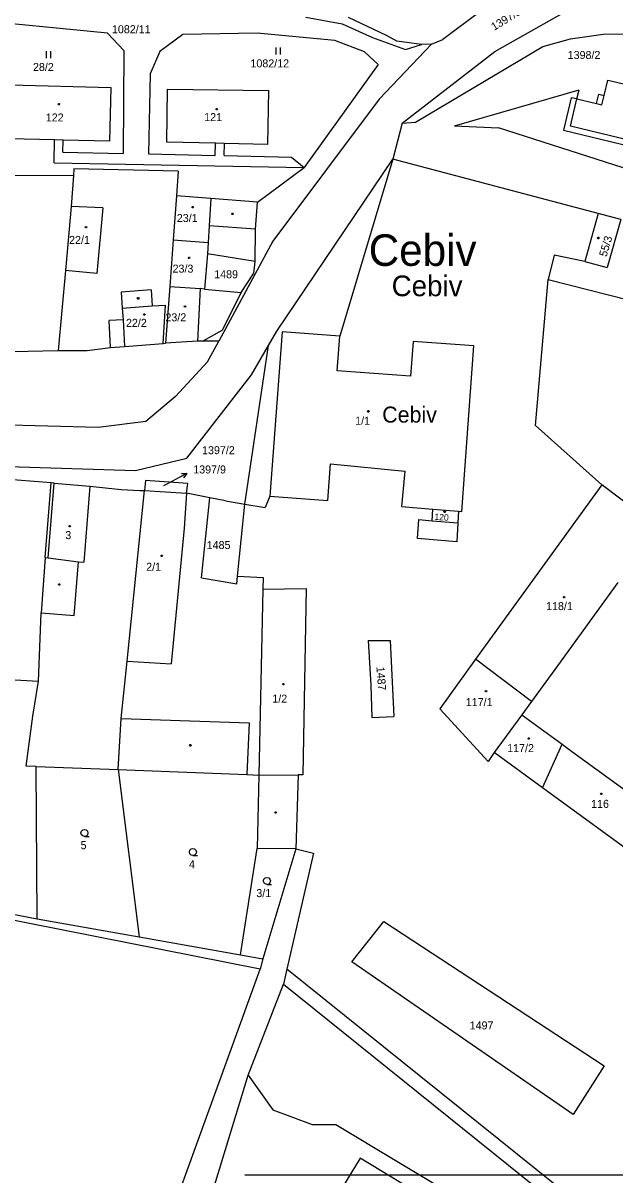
# Model space of a CAD drawing. Extents: x -852001 to -842497, y -1063614 to -1052182.
# Drawn here: x -849422.1 to -849296.3, y -1056500 to -1056255.4 of the extents above; entities that cross this region are included whole.
import ezdxf

# ---------------------------------------------------------------- set-up
doc = ezdxf.new("R2010")
doc.units = 0
for name, color, linetype in [('Default', 7, 'Continuous'), ('KLADY_ZMVM', 7, 'Continuous'), ('KN_HRANICE', 7, 'Continuous'), ('KN_KULTURY', 7, 'Continuous'), ('KN_PARCELY', 7, 'Continuous'), ('KN_SLUCKY', 7, 'Continuous')]:
    doc.layers.add(name, color=color, linetype=linetype)

# ---------------------------------------------------------------- blocks, each defined once
blk = doc.blocks.new('304')
at = {"layer": 'Default'}
blk.add_lwpolyline([(0, 0), (-0.38, 0.1), (-0.65, 0.37), (-0.75, 0.74), (-0.65, 1.11), (-0.38, 1.38), (-0.01, 1.48), (0.36, 1.38), (0.63, 1.11), (0.73, 0.73), (0.63, 0.35), (0.36, 0.08), (-0.02, -0.02), (0.98, -0.02)], dxfattribs=at)
blk = doc.blocks.new('306')
at = {"layer": 'Default'}
for p, q in [((-0.5, 1.5), (-0.5, 0)), ((0.5, 0), (0.5, 1.5))]:
    blk.add_line(p, q, dxfattribs=at)
blk = doc.blocks.new('NAHRADNI_SYMBOL')
at = {"layer": 'Default'}
blk.add_lwpolyline([(0.09, 0.15), (0.18, 0), (0.09, -0.15), (-0.09, -0.15), (-0.18, 0), (-0.09, 0.15), (0.09, 0.15)], dxfattribs=at)
blk = doc.blocks.new('10292')
at = {"layer": 'Default'}
blk.add_line((0, 3), (0, 0), dxfattribs=at)
blk.add_lwpolyline([(-0.5, 2), (0, 3), (0.5, 2)], dxfattribs=at)
blk = doc.blocks.new('402')
at = {"layer": 'Default'}
blk.add_lwpolyline([(0.09, 0.15), (0.18, 0), (0.09, -0.15), (-0.09, -0.15), (-0.18, 0), (-0.09, 0.15), (0.09, 0.15)], dxfattribs=at)

msp = doc.modelspace()

# ---------------------------------------------------------------- linework, layer by layer
at = {"layer": 'KLADY_ZMVM'}
msp.add_lwpolyline([(-849375, -1056500), (-848750, -1056500), (-848750, -1056000)], dxfattribs=at)
at = {"layer": 'KN_HRANICE'}
for p, q in [((-849321.82, -1056261.46), (-849300.76, -1056249.55)), ((-849324.78, -1056252.85), (-849332.91, -1056258.92)), ((-849362.03, -1056254.15), (-849354.27, -1056255.62)), ((-849344.89, -1056258.04), (-849352.94, -1056254.24)), ((-849404.18, -1056257.55), (-849424.4, -1056255.6)), ((-849400.7, -1056261.28), (-849404.18, -1056257.55)), ((-849388.12, -1056257.84), (-849393.05, -1056261.45)), ((-849372.35, -1056257.55), (-849388.12, -1056257.84)), ((-849355.83, -1056259.12), (-849372.35, -1056257.55)), ((-849354.27, -1056255.62), (-849347.82, -1056258.48)), ((-849305.78, -1056258.79), (-849298.81, -1056257.8)), ((-849298.81, -1056257.8), (-849292.01, -1056257.69)), ((-849349.55, -1056261.51), (-849355.83, -1056259.12)), ((-849347.82, -1056258.48), (-849340.83, -1056261.01)), ((-849335.32, -1056259.89), (-849346.41, -1056271.62)), ((-849342.67, -1056259.27), (-849344.89, -1056258.04)), ((-849337.4, -1056259.96), (-849342.67, -1056259.27)), ((-849340.83, -1056261.01), (-849337.4, -1056259.96)), ((-849335.32, -1056259.89), (-849337.4, -1056259.96)), ((-849335.32, -1056259.89), (-849332.91, -1056258.92)), ((-849311.64, -1056260.39), (-849305.78, -1056258.79)), ((-849400.7, -1056261.28), (-849400.81, -1056283.1)), ((-849393.05, -1056261.45), (-849395.08, -1056266.18)), ((-849346.61, -1056264.23), (-849349.55, -1056261.51)), ((-849341.54, -1056276.65), (-849321.82, -1056261.46)), ((-849338.74, -1056276.48), (-849311.64, -1056260.39)), ((-849346.61, -1056264.23), (-849362.36, -1056286.11)), ((-849395.08, -1056266.18), (-849395.45, -1056283.21)), ((-849298.64, -1056270.78), (-849297.86, -1056267.56)), ((-849297.86, -1056267.56), (-849293.85, -1056268.49)), ((-849424.78, -1056268.57), (-849403.43, -1056269.1)), ((-849403.43, -1056269.1), (-849403.71, -1056280.52)), ((-849391.56, -1056280.75), (-849391.39, -1056269.46)), ((-849391.39, -1056269.46), (-849369.95, -1056269.77)), ((-849369.95, -1056269.77), (-849370.17, -1056281.18)), ((-849330.43, -1056277.22), (-849303.93, -1056269.58)), ((-849304.4, -1056271.53), (-849303.93, -1056269.58)), ((-849346.41, -1056271.62), (-849369.03, -1056301.74)), ((-849305.65, -1056271.33), (-849307.26, -1056278.16)), ((-849304.4, -1056271.53), (-849305.65, -1056271.33)), ((-849304.4, -1056271.53), (-849300.26, -1056272.48)), ((-849300.26, -1056272.48), (-849299.77, -1056270.54)), ((-849299.77, -1056270.54), (-849298.64, -1056270.78)), ((-849341.54, -1056276.65), (-849343.49, -1056284.33)), ((-849341.54, -1056276.65), (-849338.74, -1056276.48)), ((-849330.43, -1056277.22), (-849321.06, -1056277.69)), ((-849254.33, -1056299.1), (-849321.06, -1056277.69)), ((-849307.26, -1056278.16), (-849283.7, -1056283.9)), ((-849415.41, -1056280.22), (-849425.04, -1056279.98)), ((-849415.48, -1056285.11), (-849415.41, -1056280.22)), ((-849413.55, -1056280.27), (-849415.41, -1056280.22)), ((-849413.61, -1056282.82), (-849413.55, -1056280.27)), ((-849403.71, -1056280.52), (-849413.55, -1056280.27)), ((-849381.2, -1056280.96), (-849391.56, -1056280.75)), ((-849381.26, -1056283.52), (-849381.2, -1056280.96)), ((-849379.31, -1056281), (-849381.2, -1056280.96)), ((-849379.36, -1056283.57), (-849379.31, -1056281)), ((-849370.17, -1056281.18), (-849379.31, -1056281)), ((-849413.61, -1056282.82), (-849400.81, -1056283.1)), ((-849395.45, -1056283.21), (-849381.26, -1056283.52)), ((-849379.36, -1056283.57), (-849365.06, -1056283.87)), ((-849368.16, -1056320.82), (-849343.49, -1056284.33)), ((-849365.06, -1056283.87), (-849362.36, -1056286.11)), ((-849343.49, -1056284.33), (-849354.8, -1056321.89)), ((-849299.89, -1056295.86), (-849343.49, -1056284.33)), ((-849415.48, -1056285.11), (-849362.36, -1056286.11)), ((-849411.31, -1056286.39), (-849411.38, -1056287.83)), ((-849389.17, -1056286.88), (-849411.31, -1056286.39)), ((-849389.17, -1056286.88), (-849389.51, -1056292.14)), ((-849372.28, -1056293.44), (-849362.36, -1056286.11)), ((-849429.11, -1056287.73), (-849411.38, -1056287.83)), ((-849411.38, -1056287.83), (-849411.89, -1056294.39)), ((-849411.89, -1056294.39), (-849413.11, -1056307.95)), ((-849389.51, -1056292.14), (-849390.2, -1056301.43)), ((-849382.2, -1056292.69), (-849389.51, -1056292.14)), ((-849372.28, -1056293.44), (-849382.2, -1056292.69)), ((-849372.68, -1056299.17), (-849372.28, -1056293.44)), ((-849299.89, -1056295.86), (-849302.72, -1056306.09)), ((-849295.08, -1056297.16), (-849299.89, -1056295.86)), ((-849372.79, -1056306.07), (-849372.68, -1056299.17)), ((-849390.2, -1056301.43), (-849390.94, -1056311.34)), ((-849390.2, -1056301.43), (-849382.78, -1056301.99)), ((-849369.03, -1056301.74), (-849380.49, -1056322.95)), ((-849382.78, -1056301.99), (-849382.93, -1056304.4)), ((-849382.93, -1056304.4), (-849383.52, -1056311.92)), ((-849372.79, -1056306.07), (-849382.93, -1056304.4)), ((-849373.05, -1056308.51), (-849372.79, -1056306.07)), ((-849309.23, -1056304.7), (-849310.53, -1056309.9)), ((-849302.72, -1056306.09), (-849309.23, -1056304.7)), ((-849413.11, -1056307.95), (-849414.63, -1056324.97)), ((-849375.73, -1056312.66), (-849373.05, -1056308.51)), ((-849390.94, -1056311.34), (-849391.84, -1056323.41)), ((-849390.94, -1056311.34), (-849384.46, -1056311.82)), ((-849313.23, -1056340.88), (-849310.53, -1056309.9)), ((-849310.53, -1056309.9), (-849293.26, -1056314.27)), ((-849394.9, -1056312.07), (-849401.27, -1056312.56)), ((-849401.27, -1056312.56), (-849401.01, -1056315.99)), ((-849394.9, -1056312.07), (-849394.64, -1056315.5)), ((-849383.52, -1056311.92), (-849384.46, -1056311.82)), ((-849383.52, -1056311.92), (-849375.73, -1056312.66)), ((-849379.69, -1056320.65), (-849375.73, -1056312.66)), ((-849401.01, -1056315.99), (-849400.86, -1056318.43)), ((-849394.64, -1056315.5), (-849391.81, -1056315.32)), ((-849392.34, -1056323.46), (-849391.81, -1056315.32)), ((-849400.86, -1056318.43), (-849403.83, -1056318.61)), ((-849403.52, -1056324.31), (-849403.83, -1056318.61)), ((-849379.69, -1056320.65), (-849383.92, -1056322.95)), ((-849369.95, -1056323.89), (-849368.16, -1056320.82)), ((-849400.53, -1056324.08), (-849392.34, -1056323.46)), ((-849392.34, -1056323.46), (-849391.84, -1056323.41)), ((-849385.02, -1056322.95), (-849391.84, -1056323.41)), ((-849383.92, -1056322.95), (-849385.02, -1056322.95)), ((-849380.49, -1056322.95), (-849383.92, -1056322.95)), ((-849382.88, -1056327.38), (-849380.49, -1056322.95)), ((-849374.96, -1056357.55), (-849369.95, -1056323.89)), ((-849373.58, -1056330.12), (-849369.95, -1056323.89)), ((-849355.34, -1056329.26), (-849354.8, -1056321.89)), ((-849339.2, -1056323.03), (-849339.74, -1056330.4)), ((-849326.3, -1056323.97), (-849339.2, -1056323.03)), ((-849427.65, -1056325.24), (-849414.63, -1056324.97)), ((-849414.63, -1056324.97), (-849408.44, -1056324.93)), ((-849408.44, -1056324.93), (-849403.52, -1056324.31)), ((-849403.52, -1056324.31), (-849400.53, -1056324.08)), ((-849328.87, -1056359.11), (-849326.3, -1056323.97)), ((-849382.88, -1056327.38), (-849389.7, -1056334.7)), ((-849387.32, -1056347.8), (-849373.58, -1056330.12)), ((-849339.74, -1056330.4), (-849355.34, -1056329.26)), ((-849389.7, -1056334.7), (-849396.03, -1056340.06)), ((-849406.11, -1056341.28), (-849532.06, -1056337.93)), ((-849396.03, -1056340.06), (-849406.11, -1056341.28)), ((-849299.09, -1056353.44), (-849313.23, -1056340.88)), ((-849398.2, -1056350.42), (-849387.32, -1056347.8)), ((-849457.69, -1056348.54), (-849398.2, -1056350.42)), ((-849357.35, -1056356.77), (-849356.75, -1056348.99)), ((-849356.75, -1056348.99), (-849340.97, -1056350.6)), ((-849340.97, -1056350.6), (-849341.66, -1056358.11)), ((-849416.15, -1056353.07), (-849426.94, -1056352.2)), ((-849417.42, -1056368.92), (-849416.15, -1056353.07)), ((-849415.5, -1056353.12), (-849416.15, -1056353.07)), ((-849415.5, -1056353.12), (-849407.89, -1056353.73)), ((-849396.05, -1056352.55), (-849396.28, -1056354.7)), ((-849387.11, -1056353.22), (-849396.05, -1056352.55)), ((-849387.38, -1056355.27), (-849387.11, -1056353.22)), ((-849407.89, -1056353.73), (-849401.22, -1056354.48)), ((-849401.22, -1056354.48), (-849397.3, -1056354.68)), ((-849400, -1056390.91), (-849396.28, -1056354.7)), ((-849397.3, -1056354.68), (-849396.28, -1056354.7)), ((-849396.28, -1056354.7), (-849387.38, -1056355.27)), ((-849382.44, -1056356.21), (-849387.38, -1056355.27)), ((-849299.09, -1056353.44), (-849325.93, -1056390.5)), ((-849291.34, -1056359.34), (-849299.09, -1056353.44)), ((-849384.19, -1056373.23), (-849382.44, -1056356.21)), ((-849379.1, -1056356.85), (-849382.44, -1056356.21)), ((-849379.1, -1056356.85), (-849374.96, -1056357.55)), ((-849376.53, -1056372.86), (-849374.96, -1056357.55)), ((-849374.96, -1056357.55), (-849370.64, -1056358.28)), ((-849369.64, -1056355.88), (-849370.64, -1056358.28)), ((-849369.64, -1056355.88), (-849357.35, -1056356.77)), ((-849341.66, -1056358.11), (-849335.01, -1056358.63)), ((-849335.2, -1056361.09), (-849335.01, -1056358.63)), ((-849335.01, -1056358.63), (-849329.56, -1056359.06)), ((-849329.56, -1056359.06), (-849329.72, -1056361.56)), ((-849329.56, -1056359.06), (-849328.87, -1056359.11)), ((-849338.31, -1056364.85), (-849337.97, -1056360.86)), ((-849337.97, -1056360.86), (-849335.2, -1056361.09)), ((-849329.72, -1056361.56), (-849329.95, -1056365.57)), ((-849329.95, -1056365.57), (-849338.31, -1056364.85)), ((-849417.42, -1056368.92), (-849418.27, -1056380.63)), ((-849384.19, -1056373.23), (-849376.7, -1056374.49)), ((-849376.7, -1056374.49), (-849376.53, -1056372.86)), ((-849376.53, -1056372.86), (-849371.1, -1056373.16)), ((-849371.1, -1056373.16), (-849371.15, -1056375.6)), ((-849295.68, -1056374.24), (-849308.52, -1056391.92)), ((-849371.15, -1056375.6), (-849372, -1056415.1)), ((-849418.85, -1056395.14), (-849418.27, -1056380.63)), ((-849348.73, -1056386.51), (-849348.23, -1056396.03)), ((-849348.73, -1056386.51), (-849344.08, -1056386.51)), ((-849344.08, -1056386.51), (-849343.29, -1056402.63)), ((-849401.25, -1056403.09), (-849400, -1056390.91)), ((-849325.93, -1056390.5), (-849333.53, -1056401)), ((-849314.04, -1056399.47), (-849325.93, -1056390.5)), ((-849308.52, -1056391.92), (-849314.04, -1056399.47)), ((-849434.1, -1056394.27), (-849418.85, -1056395.14)), ((-849420.01, -1056402.58), (-849418.85, -1056395.14)), ((-849348.23, -1056396.03), (-849348, -1056402.87)), ((-849314.04, -1056399.47), (-849316.13, -1056402.34)), ((-849333.53, -1056401), (-849323.3, -1056412.23)), ((-849421.41, -1056413.23), (-849420.01, -1056402.58)), ((-849401.89, -1056413.93), (-849401.25, -1056403.09)), ((-849348, -1056402.87), (-849343.29, -1056402.63)), ((-849316.13, -1056402.34), (-849321.97, -1056410.33)), ((-849316.13, -1056402.34), (-849307.54, -1056408.56)), ((-849311.74, -1056417.78), (-849307.54, -1056408.56)), ((-849307.54, -1056408.56), (-849305.54, -1056410.02)), ((-849321.97, -1056410.33), (-849323.3, -1056412.23)), ((-849311.74, -1056417.78), (-849321.97, -1056410.33)), ((-849305.54, -1056410.02), (-849282.02, -1056427.2)), ((-849419.34, -1056413.3), (-849421.41, -1056413.23)), ((-849419.09, -1056445.59), (-849419.34, -1056413.3)), ((-849419.34, -1056413.3), (-849401.89, -1056413.93)), ((-849401.89, -1056413.93), (-849374.54, -1056415)), ((-849401.89, -1056413.93), (-849397.43, -1056449.45)), ((-849374.54, -1056415), (-849372, -1056415.1)), ((-849372, -1056415.1), (-849372.33, -1056430.72)), ((-849287.91, -1056435.18), (-849311.74, -1056417.78)), ((-849375.87, -1056453.3), (-849372.33, -1056430.72)), ((-849364.14, -1056430.75), (-849372.33, -1056430.72)), ((-849364.14, -1056430.75), (-849371.16, -1056454.14)), ((-849364.14, -1056430.75), (-849360.36, -1056431.7)), ((-849360.36, -1056431.7), (-849366.02, -1056456.29)), ((-849371.72, -1056456.31), (-849483.86, -1056434.18)), ((-849439.82, -1056441.73), (-849419.09, -1056445.59)), ((-849419.09, -1056445.59), (-849397.43, -1056449.45)), ((-849352.25, -1056454.73), (-849345.45, -1056446.21)), ((-849345.45, -1056446.21), (-849298.59, -1056476.85)), ((-849397.43, -1056449.45), (-849375.87, -1056453.3)), ((-849375.87, -1056453.3), (-849371.16, -1056454.14)), ((-849371.16, -1056454.14), (-849371.72, -1056456.31)), ((-849305.2, -1056487.17), (-849352.25, -1056454.73)), ((-849392.25, -1056512.84), (-849371.72, -1056456.31)), ((-849366.02, -1056456.29), (-849366.76, -1056459.53)), ((-849289.39, -1056517.79), (-849366.02, -1056456.29)), ((-849374.29, -1056478.85), (-849366.76, -1056459.53)), ((-849366.76, -1056459.53), (-849294.89, -1056517.18)), ((-849298.59, -1056476.85), (-849305.2, -1056487.17)), ((-849398.6, -1056558.62), (-849374.29, -1056478.85)), ((-849374.29, -1056478.85), (-849369.04, -1056486.2)), ((-849369.04, -1056486.2), (-849360.68, -1056489.31)), ((-849360.68, -1056489.31), (-849355.61, -1056489.31)), ((-849355.61, -1056489.31), (-849305.18, -1056519.49)), ((-849350.46, -1056496.46), (-849365.37, -1056520.72)), ((-849313.05, -1056518.99), (-849350.46, -1056496.46))]:
    msp.add_line(p, q, dxfattribs=at)
at = {"layer": 'KN_PARCELY'}
msp.add_line((-849392.18, -1056353.64), (-849389.98, -1056352.47), dxfattribs=at)
at = {"layer": 'KN_SLUCKY'}
for p, q in [((-849305.79, -1056277.31), (-849304.4, -1056271.53)), ((-849300.26, -1056272.48), (-849299.11, -1056272.77)), ((-849299.11, -1056272.77), (-849298.64, -1056270.78)), ((-849283.98, -1056282.62), (-849305.79, -1056277.31)), ((-849405.13, -1056294.64), (-849411.89, -1056294.39)), ((-849382.2, -1056292.69), (-849382.56, -1056298.48)), ((-849405.13, -1056294.64), (-849406.45, -1056308.58)), ((-849382.56, -1056298.48), (-849382.78, -1056301.99)), ((-849372.68, -1056299.17), (-849382.56, -1056298.48)), ((-849295.08, -1056297.16), (-849297.98, -1056307.31)), ((-849302.72, -1056306.09), (-849297.98, -1056307.31)), ((-849406.45, -1056308.58), (-849413.11, -1056307.95)), ((-849384.46, -1056311.82), (-849385.02, -1056322.95)), ((-849401.01, -1056315.99), (-849394.64, -1056315.5)), ((-849400.86, -1056318.43), (-849400.53, -1056324.08)), ((-849367.07, -1056320.99), (-849369.64, -1056355.88)), ((-849354.8, -1056321.89), (-849367.07, -1056320.99)), ((-849416.77, -1056368.97), (-849415.5, -1056353.12)), ((-849407.89, -1056353.73), (-849409.18, -1056369.88)), ((-849387.38, -1056355.27), (-849387.87, -1056362.69)), ((-849387.87, -1056362.69), (-849390.59, -1056391.46)), ((-849335.2, -1056361.09), (-849329.72, -1056361.56)), ((-849417.42, -1056368.92), (-849416.77, -1056368.97)), ((-849416.77, -1056368.97), (-849410.33, -1056369.79)), ((-849411.25, -1056381.2), (-849410.33, -1056369.79)), ((-849410.33, -1056369.79), (-849409.18, -1056369.88)), ((-849371.15, -1056375.6), (-849361.91, -1056375.5)), ((-849361.91, -1056375.5), (-849362.64, -1056415.04)), ((-849418.27, -1056380.63), (-849411.25, -1056381.2)), ((-849400, -1056390.91), (-849390.59, -1056391.46)), ((-849401.25, -1056403.09), (-849374.04, -1056404)), ((-849374.04, -1056404), (-849374.54, -1056415)), ((-849372, -1056415.1), (-849363.62, -1056415.02)), ((-849363.62, -1056415.02), (-849364.14, -1056430.75)), ((-849362.64, -1056415.04), (-849363.62, -1056415.02))]:
    msp.add_line(p, q, dxfattribs=at)

# ---------------------------------------------------------------- block references
at = {"layer": 'KN_KULTURY'}
for name, p in [('306', (-849416.67, -1056262.91)), ('306', (-849367.91, -1056262.14)), ('402', (-849414.48, -1056272.63)), ('402', (-849380.96, -1056273.73)), ('402', (-849386.06, -1056294.51)), ('402', (-849377.59, -1056295.92)), ('402', (-849408.72, -1056298.76)), ('402', (-849299.87, -1056301.06)), ('402', (-849386.81, -1056305.3)), ('402', (-849397.64, -1056313.88)), ('402', (-849387.7, -1056315.61)), ('402', (-849396.34, -1056317.3)), ('402', (-849348.72, -1056337.87)), ('402', (-849332.52, -1056359.18)), ('402', (-849412.18, -1056362.25)), ('402', (-849392.64, -1056368.56)), ('402', (-849414.41, -1056374.66)), ('402', (-849307.13, -1056377.33)), ('402', (-849366.77, -1056395.79)), ('402', (-849323.74, -1056397.31)), ('402', (-849386.53, -1056408.79)), ('NAHRADNI_SYMBOL', (-849314.63, -1056407.31)), ('402', (-849299.2, -1056419.06)), ('402', (-849368.42, -1056423.03)), ('304', (-849409.05, -1056428.13)), ('304', (-849386, -1056432.17)), ('304', (-849370.26, -1056438.31))]:
    msp.add_blockref(name, p, dxfattribs=at)
at = {"layer": 'KN_PARCELY', "rotation": -62.00465099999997}
msp.add_blockref('10292', (-849389.98, -1056352.47), dxfattribs=at)

# ---------------------------------------------------------------- texts
at = {"layer": 'KN_PARCELY'}
for s, height, rotation, p in [('1397/3', 1.7, 31.742, (-849321.99, -1056257.11)), ('55/3', 1.7, 73.339, (-849298.12, -1056305.17)), ('120', 1.36, 356.151, (-849334.72, -1056360.91)), ('1487', 1.7, 274.389, (-849347.02, -1056392.15))]:
    msp.add_text(s, height=height, rotation=rotation, dxfattribs=at).set_placement(p)
for s, height, p in [('1082/11', 1.7, (-849403.21, -1056257.59)), ('1398/2', 1.7, (-849306.37, -1056263.06)), ('28/2', 1.7, (-849419.99, -1056265.61)), ('1082/12', 1.7, (-849373.78, -1056264.84)), ('122', 1.7, (-849417.27, -1056276.33)), ('121', 1.7, (-849383.61, -1056276.25)), ('23/1', 1.7, (-849389.42, -1056297.67)), ('22/1', 1.7, (-849412.32, -1056302.32)), ('Cebiv', 6.7, (-849348.64, -1056306.99)), ('23/3', 1.7, (-849390.33, -1056308.42)), ('1489', 1.7, (-849381.48, -1056309.62)), ('Cebiv', 4.4, (-849343.77, -1056313.43)), ('22/2', 1.7, (-849400.23, -1056319.93)), ('23/2', 1.7, (-849391.85, -1056318.76)), ('Cebiv', 3.4, (-849345.78, -1056340.26)), ('1/1', 1.7, (-849351.53, -1056340.71)), ('1397/2', 1.7, (-849384.06, -1056346.97)), ('1397/9', 1.7, (-849385.94, -1056351.06)), ('1397/9', 0.1, (-849392.48, -1056353.64)), ('3', 1.7, (-849413.12, -1056365)), ('1485', 1.7, (-849383.08, -1056367.11)), ('2/1', 1.7, (-849395.93, -1056371.72)), ('118/1', 1.7, (-849310.96, -1056380.07)), ('1/2', 1.7, (-849369.13, -1056399.72)), ('117/1', 1.7, (-849328.03, -1056400.45)), ('117/2', 1.7, (-849319.23, -1056410.23)), ('116', 1.7, (-849301.39, -1056422.06)), ('5', 1.7, (-849409.86, -1056430.83)), ('4', 1.7, (-849386.85, -1056434.87)), ('3/1', 1.7, (-849372.53, -1056441.01)), ('1497', 1.7, (-849327.2, -1056469.1))]:
    msp.add_text(s, height=height, dxfattribs=at).set_placement(p)

doc.saveas('drawing.dxf')
